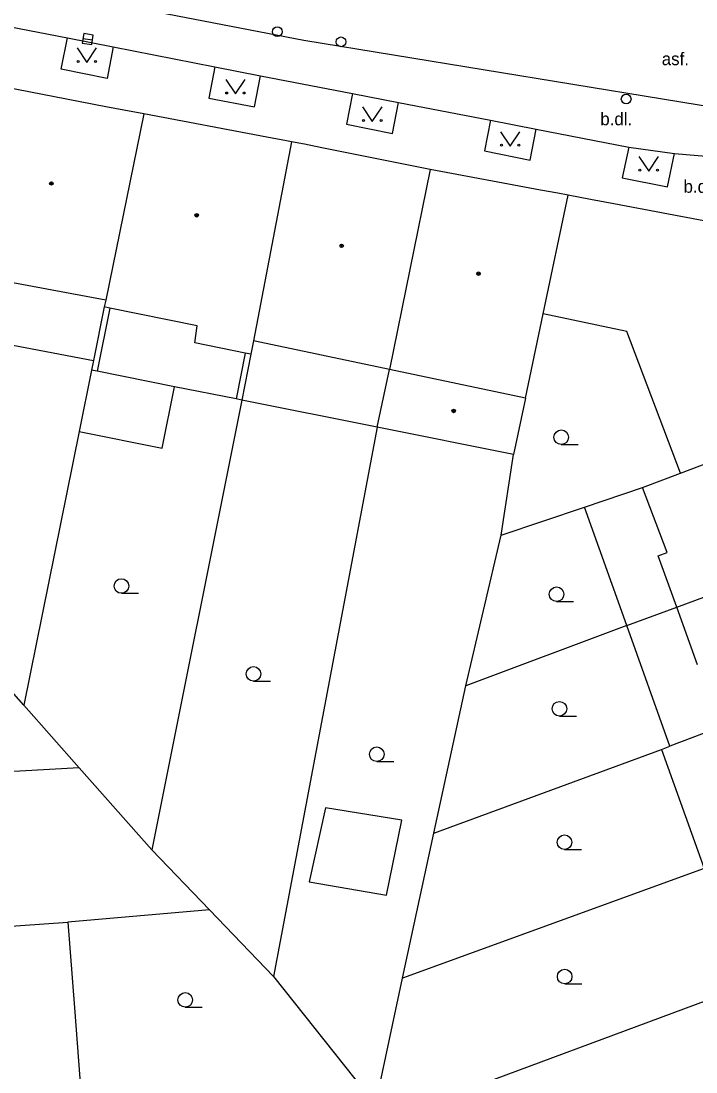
# Model space of a CAD drawing. Extents: x -596229 to -595156, y -1161237 to -1159376.
# Drawn here: x -596055.9 to -596021.2, y -1160946.5 to -1160892.5 of the extents above; entities that cross this region are included whole.
import ezdxf

# ---------------------------------------------------------------- set-up
doc = ezdxf.new("R2010")
doc.units = 0
for name, color, linetype in [('DOP - kresba z DSPS bez souradnic', 7, 'Continuous'), ('DOP - rozhrani ploch obecne', 7, 'Continuous'), ('Level 27', 7, 'Continuous'), ('Level 28', 7, 'Continuous'), ('Level 36', 7, 'Continuous'), ('Level 39', 7, 'Continuous'), ('TM - budovy zdene_ betonove - VP', 7, 'Continuous'), ('TM - chodniky - VP', 7, 'Continuous'), ('TM - komunikace - VP', 7, 'Continuous'), ('TM - letecke snimky - pomocna linie', 7, 'Continuous'), ('TM - popis povrchu', 7, 'Continuous'), ('TM - rozhrani mezi zpev. plochami mezi sebou - VP', 7, 'Continuous'), ('TM - vstup do budovy - zdene_ betonove', 7, 'Continuous')]:
    doc.layers.add(name, color=color, linetype=linetype)

msp = doc.modelspace()

# ---------------------------------------------------------------- linework, layer by layer
at = {"layer": 'DOP - kresba z DSPS bez souradnic'}
for points in [[(-596051.34, -1160907.27), (-596052, -1160910.52)], [(-596044.39, -1160909.58), (-596044.85, -1160911.94)]]:
    msp.add_lwpolyline(points, dxfattribs=at)
at = {"layer": 'DOP - rozhrani ploch obecne'}
for points in [[(-596051.64, -1160907.21), (-596052.19, -1160909.97)], [(-596059.23, -1160908.62), (-596052.19, -1160909.97)], [(-596052.19, -1160909.97), (-596052.29, -1160910.46)], [(-596044.09, -1160909.64), (-596044.56, -1160912)], [(-596052.29, -1160910.46), (-596052.93, -1160913.61)], [(-596052, -1160910.52), (-596052.29, -1160910.46)], [(-596048.02, -1160911.31), (-596052, -1160910.52)], [(-596044.85, -1160911.94), (-596048.02, -1160911.31)], [(-596044.56, -1160912), (-596049.19, -1160935.13)], [(-596044.56, -1160912), (-596044.85, -1160911.94)], [(-596037.6, -1160913.4), (-596044.56, -1160912)], [(-596052.93, -1160913.61), (-596055.77, -1160927.69)], [(-596037.6, -1160913.4), (-596042.93, -1160941.64)], [(-596031.23, -1160918.94), (-596030.6, -1160914.8)], [(-596026.95, -1160917.5), (-596023.96, -1160916.5)], [(-596031.23, -1160918.94), (-596026.95, -1160917.5)], [(-596033.05, -1160926.69), (-596031.23, -1160918.94)], [(-596024.77, -1160923.59), (-596022.2, -1160922.64)], [(-596055.77, -1160927.69), (-596059.85, -1160923.07)], [(-596024.77, -1160923.59), (-596033.05, -1160926.69)], [(-596022.55, -1160929.79), (-596024.77, -1160923.59)], [(-596034.69, -1160934.26), (-596033.05, -1160926.69)], [(-596052.93, -1160930.9), (-596055.77, -1160927.69)], [(-596019.65, -1160928.69), (-596022.55, -1160929.79)], [(-596034.69, -1160934.26), (-596022.99, -1160929.96)], [(-596022.99, -1160929.96), (-596022.55, -1160929.79)], [(-596022.99, -1160929.96), (-596020.79, -1160936.08)], [(-596052.93, -1160930.9), (-596065.15, -1160931.59)], [(-596049.19, -1160935.13), (-596052.93, -1160930.9)], [(-596036.3, -1160941.72), (-596034.69, -1160934.26)], [(-596046.23, -1160938.21), (-596049.19, -1160935.13)], [(-596020.79, -1160936.08), (-596036.3, -1160941.72)], [(-596046.23, -1160938.21), (-596053.5, -1160938.85)], [(-596042.93, -1160941.64), (-596046.23, -1160938.21)], [(-596064.48, -1160939.62), (-596053.5, -1160938.85)], [(-596053.5, -1160938.85), (-596053.16, -1160943.24)], [(-596042.93, -1160941.64), (-596038.21, -1160947.56)], [(-596037.67, -1160948.17), (-596036.3, -1160941.72)], [(-596018.26, -1160941.98), (-596036.99, -1160948.94)], [(-596053.16, -1160943.24), (-596052.76, -1160948.69)]]:
    msp.add_lwpolyline(points, dxfattribs=at)
at = {"layer": 'Level 27'}
msp.add_line((-596052.727, -1160893.404), (-596052.233, -1160893.476), dxfattribs=at)
msp.add_lwpolyline([(-596052.763, -1160893.651), (-596052.269, -1160893.723), (-596052.197, -1160893.229), (-596052.691, -1160893.157)], close=True, dxfattribs=at)
at = {"layer": 'Level 28'}
for centre in [(-596042.73, -1160893.06), (-596039.46, -1160893.58), (-596024.8, -1160896.52)]:
    msp.add_circle(centre, 0.25, dxfattribs=at)
at = {"layer": 'Level 36'}
for p, q in [((-596028.14, -1160914.285), (-596027.265, -1160914.285)), ((-596050.75, -1160921.935), (-596049.875, -1160921.935)), ((-596028.38, -1160922.355), (-596027.505, -1160922.355)), ((-596043.96, -1160926.455), (-596043.085, -1160926.455)), ((-596028.23, -1160928.245), (-596027.355, -1160928.245)), ((-596037.62, -1160930.585), (-596036.745, -1160930.585)), ((-596027.97, -1160935.105), (-596027.095, -1160935.105)), ((-596027.96, -1160942.015), (-596027.085, -1160942.015)), ((-596047.47, -1160943.215), (-596046.595, -1160943.215))]:
    msp.add_line(p, q, dxfattribs=at)
for points in [[(-596053.03, -1160893.89), (-596052.53, -1160894.64), (-596052.03, -1160893.89)], [(-596045.39, -1160895.51), (-596044.89, -1160896.26), (-596044.39, -1160895.51)], [(-596038.35, -1160896.93), (-596037.85, -1160897.68), (-596037.35, -1160896.93)], [(-596031.26, -1160898.2), (-596030.76, -1160898.95), (-596030.26, -1160898.2)], [(-596024.14, -1160899.48), (-596023.64, -1160900.23), (-596023.14, -1160899.48)]]:
    msp.add_lwpolyline(points, dxfattribs=at)
for centre, radius in [((-596052.98, -1160894.59), 0.05), ((-596052.081, -1160894.59), 0.05), ((-596045.34, -1160896.21), 0.05), ((-596044.441, -1160896.21), 0.05), ((-596038.3, -1160897.63), 0.05), ((-596037.401, -1160897.63), 0.05), ((-596031.21, -1160898.9), 0.05), ((-596030.311, -1160898.9), 0.05), ((-596024.09, -1160900.18), 0.05), ((-596023.191, -1160900.18), 0.05), ((-596028.14, -1160913.91), 0.375), ((-596050.75, -1160921.56), 0.375), ((-596028.38, -1160921.98), 0.375), ((-596043.96, -1160926.08), 0.375), ((-596028.23, -1160927.87), 0.375), ((-596037.62, -1160930.21), 0.375), ((-596027.97, -1160934.73), 0.375), ((-596027.96, -1160941.64), 0.375), ((-596047.47, -1160942.84), 0.375)]:
    msp.add_circle(centre, radius, dxfattribs=at)
at = {"layer": 'Level 39'}
for centre, radius in [((-596054.35, -1160900.86), 0.09), ((-596054.35, -1160900.86), 0.0398), ((-596046.88, -1160902.5), 0.09), ((-596046.88, -1160902.5), 0.0398), ((-596039.43, -1160904.07), 0.09), ((-596039.43, -1160904.07), 0.0398), ((-596032.39, -1160905.5), 0.09), ((-596032.39, -1160905.5), 0.0398), ((-596033.67, -1160912.56), 0.09), ((-596033.67, -1160912.56), 0.0398)]:
    msp.add_circle(centre, radius, dxfattribs=at)
at = {"layer": 'TM - budovy zdene_ betonove - VP'}
for points in [[(-596051.55, -1160896.92), (-596057.46, -1160895.78)], [(-596049.59, -1160897.29), (-596050.62, -1160897.09)], [(-596049.59, -1160897.29), (-596051.56, -1160906.86)], [(-596043.27, -1160898.48), (-596049.59, -1160897.29)], [(-596042.01, -1160898.72), (-596043.96, -1160908.95)], [(-596042.01, -1160898.72), (-596042.27, -1160898.67)], [(-596041.34, -1160898.85), (-596042.01, -1160898.72)], [(-596034.88, -1160900.15), (-596040.44, -1160899.03)], [(-596034.88, -1160900.15), (-596036.97, -1160910.43)], [(-596029.21, -1160901.2), (-596034.88, -1160900.15)], [(-596027.78, -1160901.46), (-596028.31, -1160901.36)], [(-596029.06, -1160907.56), (-596027.78, -1160901.46)], [(-596026.63, -1160901.68), (-596027.78, -1160901.46)], [(-596018.27, -1160903.27), (-596025.43, -1160901.91)], [(-596051.56, -1160906.86), (-596058.65, -1160905.54)], [(-596051.56, -1160906.86), (-596051.64, -1160907.21)], [(-596051.34, -1160907.27), (-596051.64, -1160907.21)], [(-596046.85, -1160908.18), (-596051.34, -1160907.27)], [(-596029.98, -1160911.9), (-596029.06, -1160907.56)], [(-596024.76, -1160908.47), (-596029.06, -1160907.56)], [(-596046.98, -1160909.06), (-596046.85, -1160908.18)], [(-596043.96, -1160908.95), (-596044.09, -1160909.64)], [(-596036.97, -1160910.43), (-596043.96, -1160908.95)], [(-596022, -1160915.76), (-596024.76, -1160908.47)], [(-596044.39, -1160909.58), (-596046.98, -1160909.06)], [(-596044.09, -1160909.64), (-596044.39, -1160909.58)], [(-596037.6, -1160913.4), (-596036.97, -1160910.43)], [(-596029.98, -1160911.9), (-596036.97, -1160910.43)], [(-596029.98, -1160911.9), (-596030.6, -1160914.8)], [(-596022, -1160915.76), (-596014.82, -1160913.04)], [(-596030.6, -1160914.8), (-596037.6, -1160913.4)], [(-596023.96, -1160916.5), (-596022, -1160915.76)], [(-596022.69, -1160919.84), (-596023.96, -1160916.5)], [(-596022.2, -1160922.64), (-596012.67, -1160919.11)], [(-596023.15, -1160920), (-596022.69, -1160919.84)], [(-596022.2, -1160922.64), (-596023.15, -1160920)], [(-596021.13, -1160925.62), (-596022.2, -1160922.64)]]:
    msp.add_lwpolyline(points, dxfattribs=at)
at = {"layer": 'TM - chodniky - VP'}
for points in [[(-596051.18, -1160893.84), (-596051.49, -1160895.46), (-596053.84, -1160894.99), (-596053.53, -1160893.38)], [(-596045.94, -1160894.86), (-596046.25, -1160896.48), (-596043.91, -1160896.92), (-596043.6, -1160895.32)], [(-596038.87, -1160896.23), (-596039.18, -1160897.81), (-596036.81, -1160898.29), (-596036.5, -1160896.7)], [(-596031.78, -1160897.61), (-596032.09, -1160899.19), (-596029.74, -1160899.66), (-596029.43, -1160898.07)], [(-596024.67, -1160898.99), (-596025.01, -1160900.58), (-596022.68, -1160901.04), (-596022.32, -1160899.32)]]:
    msp.add_lwpolyline(points, dxfattribs=at)
at = {"layer": 'TM - komunikace - VP'}
for points in [[(-596058.06, -1160892.5), (-596053.53, -1160893.38)], [(-596053.53, -1160893.38), (-596051.18, -1160893.84)], [(-596051.18, -1160893.84), (-596045.94, -1160894.86)], [(-596045.94, -1160894.86), (-596043.6, -1160895.32)], [(-596043.6, -1160895.32), (-596038.87, -1160896.23)], [(-596038.87, -1160896.23), (-596036.5, -1160896.7)], [(-596036.5, -1160896.7), (-596031.78, -1160897.61)], [(-596031.78, -1160897.61), (-596029.43, -1160898.07)], [(-596022.32, -1160899.32), (-596020.3, -1160899.49), (-596019.36, -1160899.49), (-596018.48, -1160899.4), (-596017.16, -1160897.3)], [(-596029.43, -1160898.07), (-596024.67, -1160898.99)], [(-596024.67, -1160898.99), (-596022.32, -1160899.32)]]:
    msp.add_lwpolyline(points, dxfattribs=at)
at = {"layer": 'TM - letecke snimky - pomocna linie'}
for points in [[(-596052.93, -1160913.61), (-596048.66, -1160914.47), (-596048.02, -1160911.31)], [(-596024.77, -1160923.59), (-596026.95, -1160917.5)], [(-596036.34, -1160933.59), (-596040.25, -1160932.96), (-596041.1, -1160936.77), (-596037.13, -1160937.45)], [(-596037.13, -1160937.45), (-596036.34, -1160933.59)]]:
    msp.add_lwpolyline(points, dxfattribs=at)
at = {"layer": 'TM - rozhrani mezi zpev. plochami mezi sebou - VP'}
msp.add_lwpolyline([(-596017.16, -1160897.3), (-596018.32, -1160897.29), (-596041.38, -1160893.52), (-596056.32, -1160890.61), (-596074.49, -1160887.1), (-596078.75, -1160886.3)], dxfattribs=at)
at = {"layer": 'TM - vstup do budovy - zdene_ betonove'}
for points in [[(-596050.62, -1160897.09), (-596051.55, -1160896.92)], [(-596042.27, -1160898.67), (-596043.27, -1160898.48)], [(-596040.44, -1160899.03), (-596041.34, -1160898.85)], [(-596028.31, -1160901.36), (-596029.21, -1160901.2)], [(-596025.43, -1160901.91), (-596026.63, -1160901.68)]]:
    msp.add_lwpolyline(points, dxfattribs=at)

# ---------------------------------------------------------------- texts
at = {"layer": 'TM - popis povrchu'}
for s, p in [('asf.', (-596022.97, -1160894.78)), ('b.dl.', (-596026.13, -1160897.87)), ('b.dl.', (-596021.85, -1160901.34))]:
    msp.add_text(s, height=0.65, dxfattribs=at).set_placement(p)

doc.saveas('drawing.dxf')
